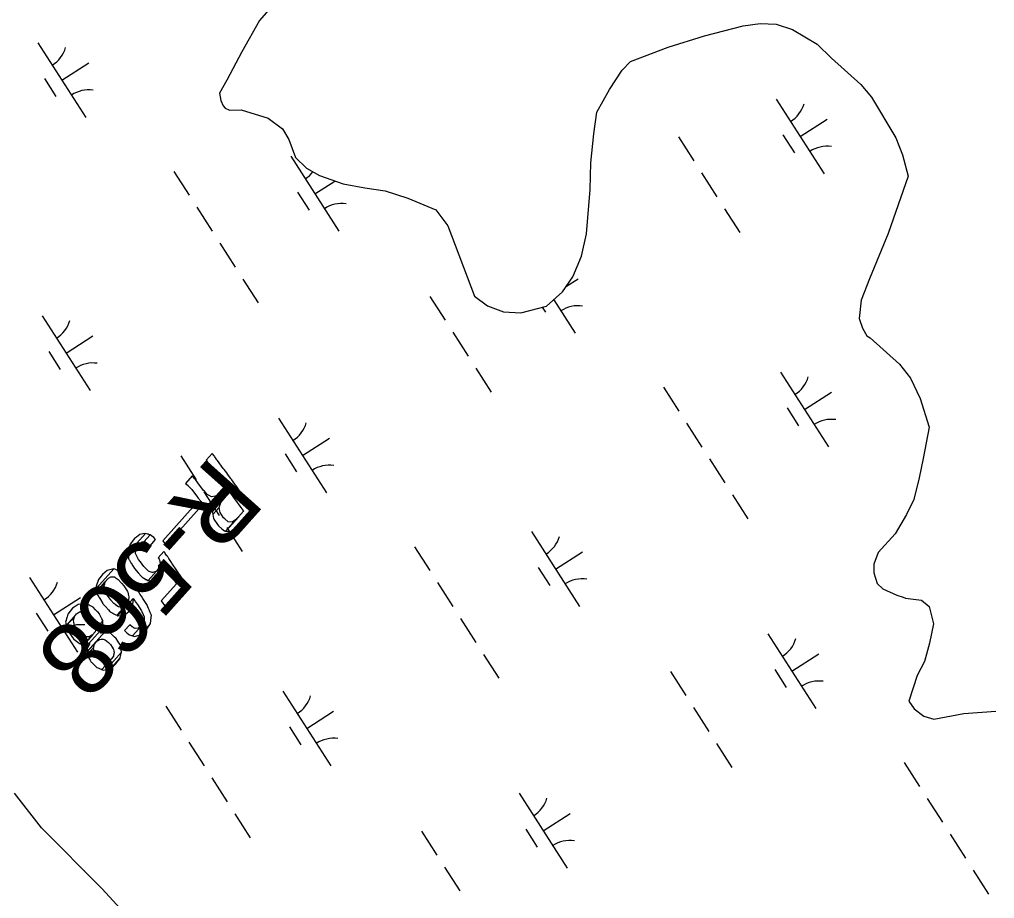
# Model space of a CAD drawing. Extents: x 3962991 to 3983549, y 181631 to 204078.
# Drawn here: x 3975877 to 3976425, y 192782 to 193277 of the extents above; entities that cross this region are included whole.
import ezdxf

# ---------------------------------------------------------------- set-up
doc = ezdxf.new("R2010")
doc.units = 0
for name, color, linetype in [('V-ANNO-MASK', 7, 'Continuous'), ('V-ANNO-MASK2', 7, 'Continuous'), ('V-RIVR-RANG-IDEN', 7, 'Continuous'), ('V-WETL-SWMP', 7, 'Continuous')]:
    doc.layers.add(name, color=color, linetype=linetype)

msp = doc.modelspace()

# ---------------------------------------------------------------- linework, layer by layer
at = {"layer": 'V-ANNO-MASK2'}
for points in [[(3975986.49, 193031.37), (3975985.31, 193032.99), (3975981.88, 193029.16), (3975983.07, 193027.54), (3975983.32, 193027.2), (3975984.53, 193025.55), (3975984.89, 193025.05), (3975988.09, 193020.7), (3975988.49, 193020.15), (3975989.98, 193018.11), (3975990.6, 193017.28), (3975991.58, 193015.94), (3975992.28, 193014.97), (3975992.5, 193014.67), (3975992.69, 193014.41), (3975983.31, 193003.91), (3975984.95, 193004.01), (3975987.56, 193005.45), (3975986.4, 193003.63), (3975985.3, 193000.53), (3975985.35, 193000.16), (3975995.12, 193011.09), (3975995.24, 193010.94), (3975995.87, 193010.08), (3975996.91, 193008.66), (3975997.24, 193008.2), (3975999.33, 193005.36), (3975999.87, 193004.61), (3976001.43, 193002.5), (3976002.56, 193000.96), (3976002.79, 193000.63), (3976002.8, 193000.64), (3976002.89, 193000.5), (3976002.94, 193000.43), (3975992.86, 192989.15), (3975996.49, 192988.93), (3975999.81, 192990.78), (3976002.9, 192993.98), (3976008.94, 193000.74), (3976008.83, 193000.88), (3976008.09, 193001.91), (3976006.36, 193004.27), (3976006.32, 193004.33), (3976006.21, 193004.46), (3976005.98, 193004.78), (3976004.85, 193006.33), (3976003.3, 193008.44), (3976002.75, 193009.19), (3976000.67, 193012.03), (3976000.33, 193012.49), (3975999.29, 193013.91), (3975998.66, 193014.77), (3975998.55, 193014.93), (3975998.37, 193015.17), (3975997.62, 193016.19), (3975997.41, 193016.48), (3975996.82, 193017.29), (3975996.12, 193018.25), (3975995.93, 193018.51), (3975995.71, 193018.81), (3975995, 193019.77), (3975994.02, 193021.11), (3975993.41, 193021.95), (3975991.91, 193023.98), (3975991.51, 193024.53), (3975988.32, 193028.89), (3975987.96, 193029.39), (3975986.74, 193031.03)], [(3975975.3, 193018.85), (3975973.94, 193020.27), (3975970.21, 193016.08), (3975971.7, 193014.81), (3975971.99, 193014.51), (3975973.36, 193013.04), (3975973.73, 193012.56), (3975976.99, 193008.28), (3975977.4, 193007.73), (3975979.1, 193005.94), (3975979.81, 193005.2), (3975981.28, 193004.42), (3975982.35, 193003.85), (3975982.87, 193003.89), (3975983.31, 193003.91), (3975989.46, 193010.79), (3975987.44, 193009), (3975986.85, 193008.89), (3975984.96, 193008.53), (3975983.47, 193009.29), (3975982.52, 193009.77), (3975980.88, 193011.62), (3975980.43, 193012.13), (3975977.24, 193016.48), (3975976.86, 193016.96), (3975975.59, 193018.54)], [(3975990.18, 193005.27), (3975992.32, 193007.95), (3975985.35, 193000.16), (3975985.39, 192999.91), (3975985.59, 192998.57), (3975989.13, 193002.54)], [(3975977.92, 193001.9), (3975976.02, 193004.49), (3975957.49, 192983.75), (3975959.39, 192981.16)], [(3975989.53, 193000.4), (3975989.13, 193002.53), (3975985.59, 192998.57), (3975985.92, 192996.35), (3975986.24, 192995.88), (3975988.23, 192992.94), (3975988.75, 192992.16), (3975990.77, 192990.58), (3975992.25, 192989.42), (3975992.55, 192989.17), (3975992.76, 192989.16), (3975998.41, 192995.48), (3975997.86, 192995.11), (3975996.54, 192994.22), (3975994.23, 192994.44), (3975992.3, 192996.13), (3975991.61, 192996.72), (3975989.66, 192999.71)], [(3976000.17, 192997.33), (3975998.41, 192995.48), (3975992.76, 192989.16), (3975992.86, 192989.15)], [(3975942.6, 192985.78), (3975941.62, 192985.04), (3975939.14, 192981.91), (3975938.66, 192980.63), (3975937.7, 192978.11), (3975937.84, 192976.89), (3975947.73, 192987.96), (3975946.21, 192987.63), (3975944.6, 192987.29)], [(3975948.99, 192987.56), (3975947.73, 192987.95), (3975937.84, 192976.89), (3975938.02, 192975.28), (3975943.74, 192981.68), (3975945.45, 192982.9), (3975945.77, 192983.12), (3975946.75, 192983.11), (3975946.76, 192983.11), (3975946.87, 192983.11), (3975950.44, 192987.1), (3975950.35, 192987.13), (3975949.57, 192987.38), (3975949.48, 192987.41)], [(3975950.89, 192986.76), (3975950.44, 192987.1), (3975946.87, 192983.11), (3975947.62, 192983.09), (3975947.78, 192983), (3975949.17, 192982.13), (3975949.22, 192982.08), (3975950.33, 192980.96), (3975953.42, 192984.42), (3975952.38, 192985.61), (3975952.33, 192985.67), (3975951.04, 192986.64)], [(3975942.3, 192979.37), (3975943.74, 192981.68), (3975938.02, 192975.28), (3975938.09, 192974.66), (3975938.1, 192974.54), (3975938.21, 192973.55), (3975938.26, 192973.47), (3975938.57, 192972.96), (3975938.67, 192972.8), (3975939.54, 192971.35), (3975939.58, 192971.28), (3975940.59, 192969.62), (3975941.5, 192968.11), (3975943.57, 192965.76), (3975945.46, 192963.6), (3975945.6, 192963.45), (3975946.13, 192963.14), (3975946.56, 192962.89), (3975947.98, 192962.05), (3975948.28, 192961.88), (3975949.02, 192961.44), (3975949.02, 192961.45), (3975949.18, 192961.35), (3975953.94, 192966.67), (3975953.56, 192966.52), (3975951.84, 192965.87), (3975951.49, 192965.99), (3975949.85, 192966.57), (3975949.35, 192966.74), (3975948.91, 192967.16), (3975948.77, 192967.3), (3975946.71, 192969.28), (3975944.84, 192971.85), (3975943.82, 192973.23), (3975942.94, 192975.05), (3975942.9, 192975.12), (3975942.14, 192976.68), (3975942.16, 192976.99), (3975942.22, 192977.9), (3975942.23, 192978.04), (3975942.3, 192979.24)], [(3975958.25, 192977.61), (3975958.13, 192977.78), (3975954.91, 192974.18), (3975955.02, 192974), (3975955.33, 192973.44), (3975955.59, 192972.99), (3975955.97, 192971), (3975955.82, 192970.32), (3975955.82, 192970.32), (3975955.45, 192968.64), (3975953.94, 192966.67), (3975949.19, 192961.35), (3975949.48, 192961.17), (3975950.62, 192961.21), (3975958.26, 192969.77), (3975959.04, 192968.64), (3975959.34, 192968.2), (3975959.56, 192967.87), (3975965.19, 192959.62), (3975956.56, 192949.95), (3975958.97, 192946.66), (3975970.53, 192959.61), (3975968.22, 192963), (3975962.59, 192971.25), (3975962.36, 192971.58), (3975962.06, 192972.03), (3975961.29, 192973.16), (3975960.82, 192973.86), (3975960.62, 192974.14), (3975960.5, 192974.3), (3975960.02, 192975.02), (3975959.82, 192975.31), (3975958.88, 192976.68), (3975958.6, 192977.1)], [(3975924.85, 192965.89), (3975923.57, 192964.8), (3975921.3, 192961.92), (3975921.1, 192961.35), (3975921.1, 192961.36), (3975919.97, 192958.16), (3975920.11, 192957.1), (3975929.83, 192967.98), (3975928.39, 192967.59), (3975926.13, 192966.99)], [(3975931.06, 192967.52), (3975929.83, 192967.97), (3975920.11, 192957.1), (3975920.33, 192955.51), (3975926.46, 192962.37), (3975926.93, 192962.66), (3975928.21, 192963.43), (3975928.98, 192963.42), (3975929.23, 192963.42), (3975930.22, 192963.41), (3975930.91, 192962.94), (3975931.3, 192962.67), (3975932.43, 192961.89), (3975934.05, 192960.11), (3975934.39, 192959.74), (3975935.39, 192958.63), (3975935.51, 192958.46), (3975936.97, 192956.19), (3975937.64, 192955.14), (3975937.7, 192954.91), (3975937.71, 192954.92), (3975938.23, 192952.97), (3975938.43, 192952.21), (3975938.14, 192950.12), (3975938.11, 192949.87), (3975936.78, 192947.71), (3975931.51, 192941.81), (3975931.89, 192941.59), (3975932.02, 192941.6), (3975940.74, 192951.36), (3975940.76, 192951.33), (3975941.61, 192950.12), (3975942.18, 192949.32), (3975942.34, 192949.09), (3975943.18, 192947.88), (3975945.45, 192944.35), (3975945.5, 192944.25), (3975945.59, 192944.05), (3975946.37, 192942.26), (3975946.91, 192941.01), (3975946.91, 192940.81), (3975946.93, 192940.04), (3975946.96, 192938.34), (3975946.64, 192937.78), (3975945.66, 192936.04), (3975940.49, 192930.24), (3975940.61, 192930.19), (3975940.61, 192930.19), (3975941.33, 192929.92), (3975944.89, 192930.83), (3975950.51, 192937.12), (3975950.9, 192940.63), (3975951.04, 192941.86), (3975950.98, 192941.99), (3975950.8, 192942.43), (3975950.75, 192942.58), (3975950.26, 192943.77), (3975950.04, 192944.31), (3975949.98, 192944.46), (3975949.46, 192945.72), (3975948.72, 192947.55), (3975948.63, 192947.76), (3975948.57, 192947.85), (3975946.26, 192951.33), (3975945.44, 192952.56), (3975945.28, 192952.79), (3975944.74, 192953.61), (3975943.91, 192954.86), (3975943.89, 192954.89), (3975943.83, 192954.96), (3975943.57, 192955.31), (3975943.29, 192955.68), (3975943.21, 192955.79), (3975942.48, 192956.75), (3975942.08, 192957.29), (3975941.05, 192958.66), (3975940.92, 192958.82), (3975940.19, 192959.79), (3975938.59, 192961.91), (3975938.45, 192962.06), (3975937.4, 192963.1), (3975937.04, 192963.45), (3975935.33, 192965.13), (3975934.35, 192966.1), (3975934.02, 192966.42), (3975933.19, 192966.73), (3975932.44, 192967.01), (3975932.25, 192967.08), (3975931.66, 192967.29), (3975931.22, 192967.46)], [(3975958.18, 192967.68), (3975958.26, 192969.77), (3975950.62, 192961.21), (3975952.46, 192961.28), (3975953.17, 192961.3), (3975954.54, 192962.25), (3975955.82, 192963.13), (3975955.83, 192963.14), (3975957.54, 192965.61), (3975957.82, 192966.51)], [(3975925.11, 192960.61), (3975926.46, 192962.37), (3975920.33, 192955.51), (3975920.36, 192955.3)], [(3975924.79, 192959.6), (3975925.1, 192960.61), (3975920.36, 192955.3), (3975920.43, 192954.72), (3975920.53, 192953.97), (3975920.57, 192953.72), (3975920.96, 192953.05), (3975921.41, 192952.3), (3975921.65, 192951.88), (3975922.39, 192950.64), (3975923.66, 192948.48), (3975924, 192948.1), (3975924.99, 192946.98), (3975924.99, 192946.99), (3975925.13, 192946.84), (3975926.87, 192944.88), (3975927.67, 192943.98), (3975927.8, 192943.83), (3975929.32, 192943), (3975929.91, 192942.68), (3975930.98, 192942.1), (3975931.1, 192942.03), (3975931.51, 192941.81), (3975936.78, 192947.71), (3975935.24, 192946.66), (3975934.76, 192946.33), (3975933.29, 192946.46), (3975932.48, 192946.53), (3975931.12, 192947.54), (3975930.96, 192947.67), (3975930, 192948.38), (3975928.3, 192950.39), (3975928.17, 192950.54), (3975927.2, 192951.69), (3975926.93, 192952.14), (3975925.65, 192954.29), (3975924.91, 192955.52), (3975924.8, 192956.1), (3975924.6, 192957.12), (3975924.42, 192958.03), (3975924.37, 192958.26)], [(3975940.74, 192951.31), (3975940.74, 192951.36), (3975932.02, 192941.6), (3975932.07, 192941.61), (3975934.17, 192941.78), (3975935.55, 192941.89), (3975936.63, 192942.71), (3975938.28, 192943.95), (3975940.11, 192946.6), (3975940.25, 192947.16), (3975940.77, 192949.17)], [(3975907.58, 192946.45), (3975906.64, 192945.83), (3975904.04, 192942.48), (3975903.62, 192940.96), (3975902.77, 192937.88), (3975903.21, 192936.18), (3975908.95, 192942.61), (3975909.45, 192942.94), (3975909.5, 192942.97), (3975910.57, 192943.68), (3975911.44, 192943.78), (3975912.78, 192943.94), (3975913.45, 192943.64), (3975913.91, 192943.42), (3975915.12, 192942.84), (3975915.19, 192942.81), (3975916.56, 192941.4), (3975917.68, 192940.24), (3975917.71, 192940.2), (3975918.49, 192938.97), (3975918.65, 192938.71), (3975919.48, 192937.38), (3975919.74, 192936.04), (3975919.77, 192935.89), (3975919.98, 192934.77), (3975919.86, 192934.35), (3975923.78, 192938.74), (3975923.68, 192938.91), (3975923.24, 192939.78), (3975923.18, 192939.9), (3975922.65, 192940.93), (3975921.92, 192942.38), (3975921.78, 192942.65), (3975920.82, 192943.68), (3975920.78, 192943.71), (3975919.67, 192944.89), (3975918.32, 192946.32), (3975918.27, 192946.37), (3975917.08, 192946.97), (3975916.62, 192947.19), (3975915.97, 192947.51), (3975915.13, 192947.92), (3975914.6, 192948.19), (3975914.29, 192948.34), (3975914.28, 192948.34), (3975914.06, 192948.32), (3975911.94, 192948.14), (3975909.87, 192947.96)], [(3975907.86, 192941.16), (3975908.95, 192942.61), (3975903.22, 192936.18), (3975903.26, 192936), (3975903.26, 192936.01), (3975903.26, 192935.99), (3975907.77, 192941.04)], [(3975907.56, 192940.31), (3975907.77, 192941.04), (3975903.26, 192935.99), (3975903.36, 192935.61), (3975903.36, 192935.61), (3975903.54, 192934.94), (3975903.8, 192933.9), (3975904.01, 192933.07), (3975904.31, 192932.67), (3975905.08, 192931.6), (3975905.12, 192931.54), (3975906.29, 192929.9), (3975906.29, 192929.91), (3975907.25, 192928.56), (3975907.29, 192928.53), (3975908.41, 192927.68), (3975908.63, 192927.51), (3975908.64, 192927.51), (3975909.84, 192926.59), (3975910.7, 192925.93), (3975910.8, 192925.85), (3975911.85, 192925.67), (3975912.07, 192925.63), (3975912.49, 192925.55), (3975913.02, 192925.46), (3975913.17, 192925.43), (3975917.96, 192930.79), (3975917.57, 192930.56), (3975916.28, 192929.79), (3975915.77, 192929.77), (3975915.51, 192929.76), (3975914.25, 192929.71), (3975914.07, 192929.7), (3975913.1, 192930.24), (3975911.75, 192930.99), (3975911.55, 192931.21), (3975910.61, 192932.25), (3975910.58, 192932.29), (3975909.49, 192933.48), (3975908.42, 192935.23), (3975908.38, 192935.3), (3975907.68, 192936.44), (3975907.56, 192937.05), (3975907.39, 192937.91), (3975907.17, 192939.01)], [(3975923.78, 192938.2), (3975923.77, 192938.73), (3975919.86, 192934.35), (3975919.62, 192933.54), (3975919.33, 192932.53), (3975917.96, 192930.79), (3975913.18, 192925.44), (3975913.9, 192925.3), (3975915.78, 192925.86), (3975923.84, 192934.88), (3975923.81, 192936.4), (3975923.8, 192937.32), (3975923.79, 192937.53)], [(3975923.4, 192933.94), (3975923.84, 192934.88), (3975915.78, 192925.86), (3975916.33, 192926.02), (3975915.16, 192923.65), (3975914.84, 192923.01), (3975914.9, 192921.42), (3975924.76, 192932.46), (3975922.74, 192931.85), (3975922.39, 192931.75)], [(3975940.15, 192935.3), (3975938.86, 192936.52), (3975935.91, 192933.22), (3975937.21, 192932.01), (3975938.11, 192931.17), (3975938.21, 192931.07), (3975938.75, 192930.88), (3975939.91, 192930.45), (3975940.05, 192930.4), (3975940.49, 192930.24), (3975945.67, 192936.04), (3975943.85, 192934.64), (3975943.64, 192934.62), (3975941.87, 192934.37), (3975941.39, 192934.63), (3975941.26, 192934.7)], [(3975950.25, 192936.73), (3975950.5, 192937.11), (3975944.89, 192930.83), (3975944.99, 192930.85), (3975948.03, 192933.44), (3975948.03, 192933.44)], [(3975924.96, 192932.41), (3975924.76, 192932.45), (3975914.9, 192921.42), (3975914.91, 192921.17), (3975920.3, 192927.2), (3975920.72, 192927.48), (3975921.87, 192928.26), (3975922.7, 192928.34), (3975923.16, 192928.38), (3975923.16, 192928.38), (3975923.97, 192928.45), (3975924.55, 192928.14), (3975924.94, 192927.92), (3975924.94, 192927.92), (3975926.05, 192927.3), (3975926.94, 192926.42), (3975927.22, 192926.13), (3975927.98, 192925.36), (3975928.05, 192925.3), (3975929.01, 192923.83), (3975929.62, 192922.89), (3975929.63, 192922.84), (3975929.92, 192921.55), (3975929.93, 192921.55), (3975930.05, 192921.03), (3975930.12, 192920.68), (3975929.78, 192919.35), (3975929.79, 192919.36), (3975929.64, 192918.8), (3975928.4, 192917.14), (3975923.2, 192911.32), (3975923.96, 192911.02), (3975925.57, 192911.36), (3975934.31, 192921.13), (3975934.1, 192922.37), (3975933.93, 192923.34), (3975933.9, 192923.56), (3975933.84, 192923.89), (3975933.71, 192924.69), (3975933.64, 192925.05), (3975933.4, 192925.44), (3975932.78, 192926.37), (3975932.75, 192926.4), (3975932.14, 192927.33), (3975931.17, 192928.79), (3975931.11, 192928.87), (3975930.3, 192929.58), (3975930, 192929.85), (3975929.07, 192930.67), (3975928.13, 192931.49), (3975927.8, 192931.78), (3975927.08, 192931.94), (3975926.46, 192932.08), (3975926.11, 192932.16), (3975925.48, 192932.3), (3975925.1, 192932.38)], [(3975919.08, 192925.65), (3975920.3, 192927.2), (3975914.91, 192921.17), (3975914.92, 192920.99), (3975914.94, 192920.5), (3975914.97, 192919.68), (3975918.46, 192923.59), (3975918.85, 192924.88)], [(3975918.54, 192923.21), (3975918.45, 192923.58), (3975914.97, 192919.68), (3975914.98, 192919.23), (3975915.28, 192918.73), (3975915.63, 192918.16), (3975915.86, 192917.76), (3975916.53, 192916.64), (3975917.2, 192915.51), (3975917.49, 192915.24), (3975918.26, 192914.48), (3975918.33, 192914.42), (3975919.54, 192913.23), (3975920.32, 192912.48), (3975920.34, 192912.45), (3975921.42, 192912.03), (3975921.86, 192911.86), (3975922.14, 192911.75), (3975922.77, 192911.5), (3975923.03, 192911.39), (3975923.2, 192911.32), (3975928.4, 192917.15), (3975927.74, 192916.67), (3975926.75, 192915.96), (3975925.8, 192915.83), (3975925.36, 192915.78), (3975924.69, 192915.69), (3975923.67, 192916.18), (3975923.64, 192916.2), (3975922.63, 192916.68), (3975921.46, 192917.92), (3975921.4, 192917.99), (3975920.65, 192918.77), (3975920.42, 192919.12), (3975919.7, 192920.19), (3975918.98, 192921.25), (3975918.87, 192921.78), (3975918.69, 192922.55)], [(3975933.42, 192918.01), (3975934.3, 192921.13), (3975925.57, 192911.36), (3975927.91, 192911.83), (3975929.21, 192912.9), (3975933.26, 192917.43)], [(3975930.94, 192914.3), (3975933.25, 192917.43), (3975929.21, 192912.9)]]:
    msp.add_lwpolyline(points, close=True, dxfattribs=at)
at = {"layer": 'V-WETL-SWMP'}
for p, q in [((3975887.11, 193264.14), (3975914.09, 193222.05)), ((3975900.6, 193243.1), (3975915.75, 193252.81)), ((3975890.86, 193243.98), (3975897.34, 193233.88)), ((3976302.61, 193232.42), (3976329.6, 193190.33)), ((3976316.1, 193211.38), (3976331.26, 193221.09)), ((3976247.71, 193211.13), (3976256.34, 193197.66)), ((3976306.37, 193212.27), (3976312.85, 193202.16)), ((3976029.55, 193200.19), (3976056.54, 193158.1)), ((3975963.67, 193191.72), (3975972.31, 193178.25)), ((3976043.05, 193179.15), (3976054.21, 193186.3)), ((3976260.66, 193190.92), (3976269.29, 193177.45)), ((3976033.31, 193180.03), (3976039.79, 193169.93)), ((3975976.63, 193171.51), (3975985.26, 193158.04)), ((3976273.61, 193170.72), (3976282.25, 193157.25)), ((3975989.58, 193151.31), (3975998.22, 193137.84)), ((3976002.53, 193131.11), (3976011.17, 193117.64)), ((3976184.62, 193127.08), (3976191.23, 193131.32)), ((3976107.67, 193121.35), (3976116.31, 193107.88)), ((3976170.99, 193115.24), (3976172.81, 193112.39)), ((3976177.44, 193119.47), (3976189.56, 193100.56)), ((3975889.52, 193110.42), (3975916.51, 193068.33)), ((3975903.02, 193089.37), (3975918.17, 193099.09)), ((3976120.63, 193101.15), (3976129.26, 193087.68)), ((3975893.28, 193090.26), (3975899.76, 193080.16)), ((3976133.58, 193080.95), (3976142.22, 193067.48)), ((3976305.03, 193078.7), (3976332.01, 193036.61)), ((3976239.15, 193070.23), (3976247.78, 193056.76)), ((3976318.52, 193057.65), (3976333.67, 193067.37)), ((3976308.79, 193058.54), (3976315.26, 193048.44)), ((3976022.55, 193052.88), (3976049.53, 193010.78)), ((3976252.1, 193050.02), (3976260.74, 193036.55)), ((3976036.04, 193031.83), (3976051.19, 193041.55)), ((3976026.31, 193032.72), (3976032.78, 193022.62)), ((3975967.64, 193031.58), (3975976.28, 193018.11)), ((3976265.05, 193029.82), (3976273.69, 193016.35)), ((3975980.6, 193011.38), (3975989.23, 192997.91)), ((3976278.01, 193009.61), (3976286.64, 192996.14)), ((3975993.55, 192991.17), (3976002.18, 192977.7)), ((3976165, 192988.93), (3976191.98, 192946.83)), ((3976099.12, 192980.45), (3976107.75, 192966.98)), ((3976178.49, 192967.88), (3976193.64, 192977.6)), ((3976168.76, 192968.77), (3976175.23, 192958.67)), ((3975882.52, 192963.1), (3975909.5, 192921.01)), ((3976112.07, 192960.25), (3976120.7, 192946.78)), ((3975896.01, 192942.06), (3975911.16, 192951.77)), ((3975886.27, 192942.94), (3975892.75, 192932.84)), ((3976125.02, 192940.04), (3976133.66, 192926.57)), ((3976298.02, 192931.38), (3976325.01, 192889.29)), ((3976137.97, 192919.84), (3976146.61, 192906.37)), ((3976311.51, 192910.34), (3976326.67, 192920.05)), ((3976243.12, 192910.09), (3976251.75, 192896.62)), ((3976301.78, 192911.23), (3976308.26, 192901.12)), ((3976024.96, 192899.15), (3976051.95, 192857.06)), ((3975959.08, 192890.68), (3975967.72, 192877.21)), ((3976256.07, 192889.88), (3976264.7, 192876.41)), ((3976038.46, 192878.11), (3976053.61, 192887.82)), ((3976028.72, 192878.99), (3976035.2, 192868.89)), ((3975972.04, 192870.47), (3975980.67, 192857)), ((3976269.02, 192869.68), (3976277.66, 192856.21)), ((3976374.59, 192858.96), (3976383.22, 192845.49)), ((3975984.99, 192850.27), (3975993.63, 192836.8)), ((3976157.99, 192841.61), (3976184.97, 192799.52)), ((3976387.54, 192838.75), (3976396.18, 192825.29)), ((3975997.94, 192830.07), (3976006.58, 192816.6)), ((3976171.48, 192820.56), (3976186.64, 192830.28)), ((3976103.08, 192820.31), (3976111.72, 192806.84)), ((3976161.75, 192821.45), (3976168.22, 192811.35)), ((3976400.5, 192818.55), (3976409.13, 192805.08)), ((3975913.32, 192797.88), (3975913.58, 192798.05)), ((3976116.04, 192800.11), (3976124.67, 192786.64)), ((3976413.45, 192798.35), (3976422.08, 192784.88))]:
    msp.add_line(p, q, dxfattribs=at)
for points in [[(3976024.46, 193291.22), (3976011.94, 193276.57), (3976001.87, 193258.93), (3975993.59, 193243.11), (3975989.45, 193235.81), (3975990.1, 193231.59), (3975991.35, 193228.58), (3975992.57, 193227.39), (3975995, 193226.21), (3976001.65, 193226.28)], [(3976001.65, 193226.28), (3976016.81, 193221.63), (3976024.74, 193215.67), (3976028.43, 193209.67), (3976032.18, 193199.44), (3976038.29, 193193.47), (3976045.59, 193189.32), (3976058.95, 193184.64), (3976071.06, 193182.37), (3976082.56, 193180.69), (3976095.3, 193176.61), (3976111.09, 193170.14), (3976117.85, 193161.15), (3976132.81, 193121.44), (3976140.13, 193116.08), (3976149.24, 193112.56), (3976158.91, 193112.07), (3976173.38, 193115.87), (3976182.35, 193123.83), (3976188.29, 193132.36), (3976192.99, 193143.9), (3976195.87, 193156.62), (3976198, 193181.43), (3976198.42, 193196.54), (3976200.05, 193212.88), (3976201.72, 193224.99), (3976208.82, 193237.76), (3976215.95, 193248.73), (3976220.73, 193253.62), (3976241.79, 193261.72), (3976262.26, 193268), (3976283.96, 193273.7), (3976293.61, 193275.02), (3976302.68, 193274.52), (3976311.78, 193271.6), (3976325.78, 193263.3), (3976333.73, 193255.54), (3976350.22, 193240.62), (3976356.35, 193233.44), (3976369.91, 193210.63), (3976373.65, 193201), (3976376.81, 193188.95), (3976365.7, 193156.79), (3976355.12, 193131.28), (3976350.43, 193119.14), (3976349.34, 193108.85), (3976351.21, 193103.43), (3976353.68, 193099.23), (3976355.51, 193098.04), (3976372, 193083.12), (3976378.14, 193075.34), (3976383.71, 193063.92), (3976388.73, 193047.66), (3976385.31, 193030.09), (3976383.02, 193019.19), (3976380.14, 193007.06), (3976376.01, 192998.55), (3976369.49, 192987.6), (3976359.94, 192977.21), (3976357.6, 192970.54), (3976357.66, 192965.7), (3976359.54, 192959.68), (3976362.6, 192956.69), (3976370.49, 192953.16), (3976374.13, 192951.99), (3976375.35, 192951.4), (3976384.43, 192950.3), (3976388.7, 192946.72), (3976391.23, 192937.08), (3976388.94, 192926.18), (3976386.04, 192915.87), (3976381.9, 192907.96), (3976377.23, 192893.4), (3976380.3, 192889.21), (3976385.79, 192885.04), (3976391.25, 192883.29), (3976408.14, 192886.51), (3976426.25, 192887.93)], [(3975935.78, 192774.42), (3975923.08, 192788.01), (3975889.24, 192822.25), (3975874.08, 192841.78)]]:
    msp.add_lwpolyline(points, dxfattribs=at)
for centre, start, end in [((3975885.89, 193266.48), 301.8919, 343.4355), ((3975915.71, 193219.97), 81.8919, 123.4355), ((3976301.4, 193234.76), 301.8919, 343.4355), ((3976331.21, 193188.25), 81.8919, 123.4355), ((3976028.34, 193202.53), 301.8919, 320.7311), ((3976058.15, 193156.02), 81.8919, 123.4355), ((3976191.18, 193098.48), 81.8919, 123.4355), ((3975888.31, 193112.75), 301.8919, 343.4355), ((3975918.12, 193066.25), 81.8919, 123.4355), ((3976303.81, 193081.04), 301.8919, 343.4355), ((3976021.33, 193055.21), 301.8919, 343.4355), ((3976333.63, 193034.53), 81.8919, 123.4355), ((3976051.15, 193008.71), 81.8919, 123.4355), ((3976163.78, 192991.26), 301.8919, 343.4355), ((3976193.6, 192944.76), 81.8919, 123.4355), ((3975881.3, 192965.44), 301.8919, 343.4355), ((3975911.12, 192918.93), 81.8919, 123.4355), ((3976296.81, 192933.72), 301.8919, 343.4355), ((3976326.62, 192887.21), 81.8919, 123.4355), ((3976023.75, 192901.49), 301.8919, 343.4355), ((3976053.56, 192854.98), 81.8919, 123.4355), ((3976156.77, 192843.95), 301.8919, 343.4355), ((3976186.59, 192797.44), 81.8919, 123.4355)]:
    msp.add_arc(centre, 17.62, start, end, dxfattribs=at)

# ---------------------------------------------------------------- texts
at = {"layer": 'V-ANNO-MASK'}
msp.add_text('R-568  ', height=41.5, rotation=228.2258, dxfattribs=at).set_placement((3975984.89, 193032.52))
at = {"layer": 'V-RIVR-RANG-IDEN'}
msp.add_text('R-568  ', height=41.5, rotation=228.2258, dxfattribs=at).set_placement((3975984.89, 193032.52))

doc.saveas('drawing.dxf')
